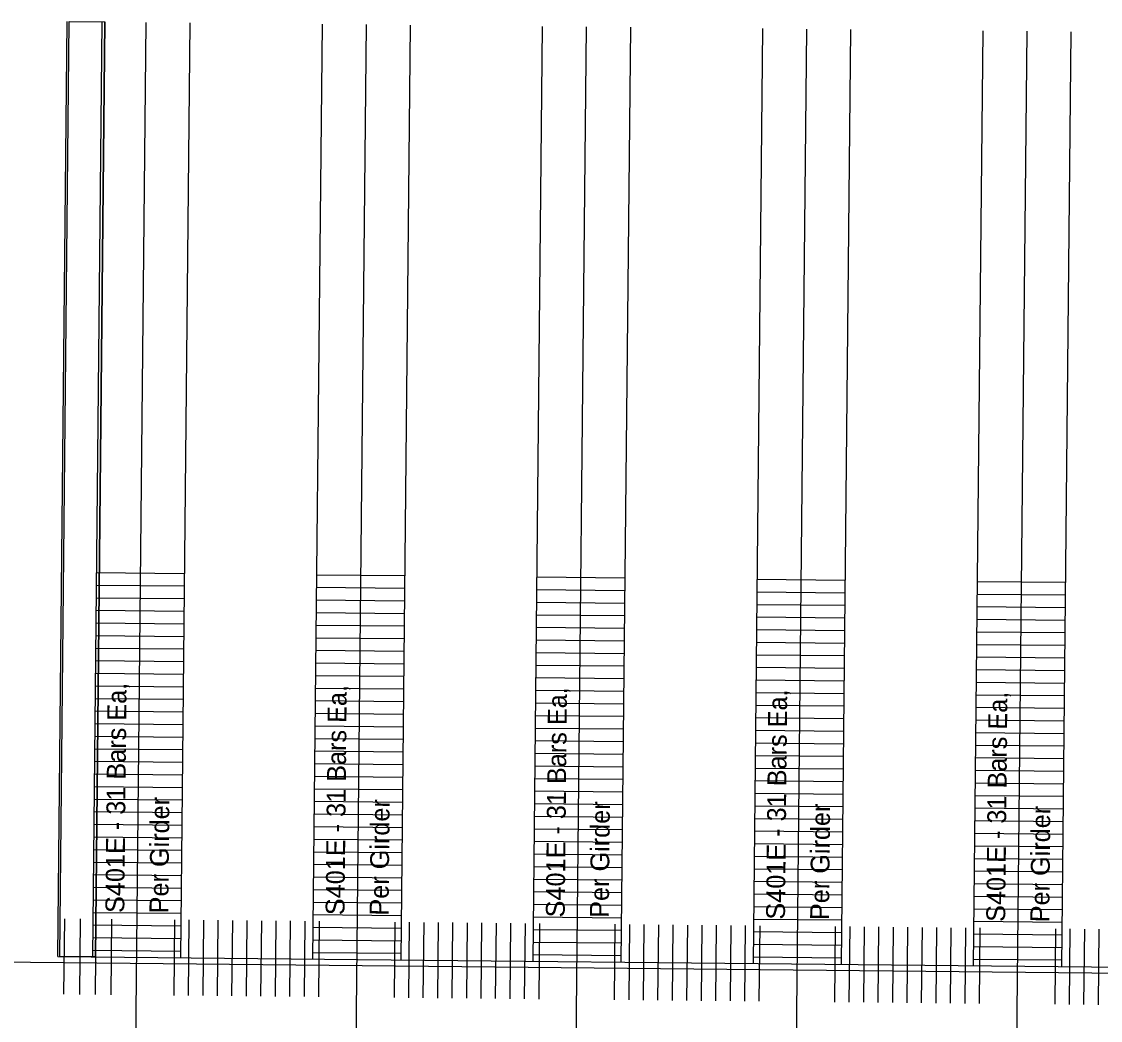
# Model space of a CAD drawing. Extents: x 632547 to 633311, y 380830 to 386139.
# Drawn here: x 633125.99 to 633168.86, y 380897.98 to 380937.66 of the extents above; entities that cross this region are included whole.
import ezdxf

# ---------------------------------------------------------------- set-up
doc = ezdxf.new("R2010")
doc.units = 0
for name, color, linetype in [('B_Border', 7, 'Continuous'), ('B_Boring Annot', 7, 'Continuous'), ('R_Border_Scale', 7, 'Continuous'), ('R_Wall', 7, 'Continuous')]:
    doc.layers.add(name, color=color, linetype=linetype)

msp = doc.modelspace()

# ---------------------------------------------------------------- linework, layer by layer
at = {"layer": 'B_Border'}
for p, q in [((633130.932, 380937.625), (633130.499, 380894.868)), ((633139.681, 380937.537), (633139.249, 380894.779)), ((633148.431, 380937.448), (633147.998, 380894.69)), ((633157.181, 380937.36), (633156.748, 380894.602)), ((633165.93, 380937.271), (633165.498, 380894.513)), ((633212.425, 380899.415), (633095.371, 380900.599))]:
    msp.add_line(p, q, dxfattribs=at)
at = {"layer": 'B_Boring Annot'}
for p, q in [((633127.431, 380900.525), (633127.807, 380937.657)), ((633127.515, 380900.524), (633127.89, 380937.656)), ((633129.182, 380937.643), (633128.806, 380900.511)), ((633128.931, 380900.51), (633129.307, 380937.642)), ((633132.682, 380937.607), (633132.306, 380900.476)), ((633137.932, 380937.554), (633137.556, 380900.423)), ((633141.431, 380937.519), (633141.056, 380900.387)), ((633146.681, 380937.466), (633146.305, 380900.334)), ((633150.181, 380937.43), (633149.805, 380900.299)), ((633155.431, 380937.377), (633155.055, 380900.246)), ((633158.93, 380937.342), (633158.555, 380900.21)), ((633164.18, 380937.289), (633163.805, 380900.157)), ((633167.68, 380937.253), (633167.304, 380900.122)), ((633127.431, 380900.525), (633212.427, 380899.665))]:
    msp.add_line(p, q, dxfattribs=at)
msp.add_lwpolyline([(633127.89, 380937.656), (633129.307, 380937.642), (633128.931, 380900.51), (633127.515, 380900.524)], close=True, dxfattribs=at)
at = {"layer": 'R_Border_Scale'}
for p, q in [((633132.46, 380915.725), (633128.961, 380915.76)), ((633141.21, 380915.636), (633137.71, 380915.672)), ((633149.96, 380915.548), (633146.46, 380915.583)), ((633132.455, 380915.225), (633128.956, 380915.26)), ((633141.205, 380915.136), (633137.705, 380915.172)), ((633158.709, 380915.459), (633155.209, 380915.495)), ((633167.459, 380915.371), (633163.959, 380915.406)), ((633132.45, 380914.725), (633128.951, 380914.76)), ((633149.955, 380915.048), (633146.455, 380915.083)), ((633158.704, 380914.959), (633155.204, 380914.995)), ((633167.454, 380914.871), (633163.954, 380914.906)), ((633141.2, 380914.636), (633137.7, 380914.672)), ((633149.949, 380914.548), (633146.45, 380914.583)), ((633158.699, 380914.459), (633155.199, 380914.495)), ((633167.449, 380914.371), (633163.949, 380914.406)), ((633132.445, 380914.225), (633128.945, 380914.26)), ((633141.195, 380914.136), (633137.695, 380914.172)), ((633149.944, 380914.048), (633146.445, 380914.083)), ((633158.694, 380913.959), (633155.194, 380913.995)), ((633167.443, 380913.871), (633163.944, 380913.906)), ((633132.44, 380913.725), (633128.94, 380913.76)), ((633141.19, 380913.637), (633137.69, 380913.672)), ((633149.939, 380913.548), (633146.44, 380913.583)), ((633158.689, 380913.459), (633155.189, 380913.495)), ((633132.435, 380913.225), (633128.935, 380913.26)), ((633141.185, 380913.137), (633137.685, 380913.172)), ((633149.934, 380913.048), (633146.434, 380913.083)), ((633158.684, 380912.96), (633155.184, 380912.995)), ((633167.438, 380913.371), (633163.939, 380913.406)), ((633132.43, 380912.725), (633128.93, 380912.76)), ((633141.18, 380912.637), (633137.68, 380912.672)), ((633149.929, 380912.548), (633146.429, 380912.583)), ((633167.433, 380912.871), (633163.934, 380912.906)), ((633132.425, 380912.225), (633128.925, 380912.261)), ((633141.175, 380912.137), (633137.675, 380912.172)), ((633158.679, 380912.46), (633155.179, 380912.495)), ((633167.428, 380912.371), (633163.928, 380912.406)), ((633132.42, 380911.725), (633128.92, 380911.761)), ((633149.924, 380912.048), (633146.424, 380912.083)), ((633158.674, 380911.96), (633155.174, 380911.995)), ((633167.423, 380911.871), (633163.923, 380911.906)), ((633141.17, 380911.637), (633137.67, 380911.672)), ((633149.919, 380911.548), (633146.419, 380911.584)), ((633158.669, 380911.46), (633155.169, 380911.495)), ((633167.418, 380911.371), (633163.918, 380911.406)), ((633132.415, 380911.225), (633128.915, 380911.261)), ((633141.164, 380911.137), (633137.665, 380911.172)), ((633149.914, 380911.048), (633146.414, 380911.084)), ((633158.664, 380910.96), (633155.164, 380910.995)), ((633167.413, 380910.871), (633163.913, 380910.906)), ((633132.41, 380910.725), (633128.91, 380910.761)), ((633141.159, 380910.637), (633137.66, 380910.672)), ((633149.909, 380910.548), (633146.409, 380910.584)), ((633158.659, 380910.46), (633155.159, 380910.495)), ((633132.405, 380910.225), (633128.905, 380910.261)), ((633141.154, 380910.137), (633137.655, 380910.172)), ((633149.904, 380910.048), (633146.404, 380910.084)), ((633158.653, 380909.96), (633155.154, 380909.995)), ((633167.408, 380910.371), (633163.908, 380910.407)), ((633132.4, 380909.725), (633128.9, 380909.761)), ((633141.149, 380909.637), (633137.649, 380909.672)), ((633149.899, 380909.548), (633146.399, 380909.584)), ((633167.403, 380909.871), (633163.903, 380909.907)), ((633132.395, 380909.225), (633128.895, 380909.261)), ((633141.144, 380909.137), (633137.644, 380909.172)), ((633158.648, 380909.46), (633155.149, 380909.495)), ((633167.398, 380909.371), (633163.898, 380909.407)), ((633132.39, 380908.725), (633128.89, 380908.761)), ((633149.894, 380909.048), (633146.394, 380909.084)), ((633158.643, 380908.96), (633155.144, 380908.995)), ((633167.393, 380908.871), (633163.893, 380908.907)), ((633141.139, 380908.637), (633137.639, 380908.672)), ((633149.889, 380908.548), (633146.389, 380908.584)), ((633158.638, 380908.46), (633155.138, 380908.495)), ((633167.388, 380908.371), (633163.888, 380908.407)), ((633132.385, 380908.225), (633128.885, 380908.261)), ((633141.134, 380908.137), (633137.634, 380908.172)), ((633149.884, 380908.048), (633146.384, 380908.084)), ((633158.633, 380907.96), (633155.133, 380907.995)), ((633167.383, 380907.871), (633163.883, 380907.907)), ((633132.38, 380907.725), (633128.88, 380907.761)), ((633141.129, 380907.637), (633137.629, 380907.672)), ((633149.879, 380907.548), (633146.379, 380907.584)), ((633158.628, 380907.46), (633155.128, 380907.495)), ((633132.374, 380907.225), (633128.875, 380907.261)), ((633141.124, 380907.137), (633137.624, 380907.172)), ((633149.874, 380907.048), (633146.374, 380907.084)), ((633158.623, 380906.96), (633155.123, 380906.995)), ((633167.378, 380907.371), (633163.878, 380907.407)), ((633132.369, 380906.725), (633128.87, 380906.761)), ((633141.119, 380906.637), (633137.619, 380906.672)), ((633149.869, 380906.548), (633146.369, 380906.584)), ((633167.373, 380906.871), (633163.873, 380906.907)), ((633132.364, 380906.225), (633128.865, 380906.261)), ((633141.114, 380906.137), (633137.614, 380906.172)), ((633158.618, 380906.46), (633155.118, 380906.495)), ((633167.368, 380906.371), (633163.868, 380906.407)), ((633132.359, 380905.725), (633128.859, 380905.761)), ((633149.863, 380906.048), (633146.364, 380906.084)), ((633158.613, 380905.96), (633155.113, 380905.995)), ((633167.363, 380905.871), (633163.863, 380905.907)), ((633141.109, 380905.637), (633137.609, 380905.672)), ((633149.858, 380905.548), (633146.359, 380905.584)), ((633158.608, 380905.46), (633155.108, 380905.495)), ((633167.357, 380905.371), (633163.858, 380905.407)), ((633132.354, 380905.225), (633128.854, 380905.261)), ((633141.104, 380905.137), (633137.604, 380905.172)), ((633149.853, 380905.048), (633146.354, 380905.084)), ((633158.603, 380904.96), (633155.103, 380904.995)), ((633167.352, 380904.871), (633163.853, 380904.907)), ((633132.349, 380904.726), (633128.849, 380904.761)), ((633141.099, 380904.637), (633137.599, 380904.672)), ((633149.848, 380904.548), (633146.348, 380904.584)), ((633158.598, 380904.46), (633155.098, 380904.495)), ((633132.344, 380904.226), (633128.844, 380904.261)), ((633141.094, 380904.137), (633137.594, 380904.172)), ((633149.843, 380904.048), (633146.343, 380904.084)), ((633158.593, 380903.96), (633155.093, 380903.995)), ((633167.347, 380904.371), (633163.848, 380904.407)), ((633132.339, 380903.726), (633128.839, 380903.761)), ((633141.089, 380903.637), (633137.589, 380903.672)), ((633149.838, 380903.549), (633146.338, 380903.584)), ((633167.342, 380903.871), (633163.843, 380903.907)), ((633132.334, 380903.226), (633128.834, 380903.261)), ((633141.084, 380903.137), (633137.584, 380903.172)), ((633158.588, 380903.46), (633155.088, 380903.495)), ((633167.337, 380903.371), (633163.837, 380903.407)), ((633132.329, 380902.726), (633128.829, 380902.761)), ((633149.833, 380903.049), (633146.333, 380903.084)), ((633158.583, 380902.96), (633155.083, 380902.995)), ((633167.332, 380902.871), (633163.832, 380902.907)), ((633141.078, 380902.637), (633137.579, 380902.672)), ((633149.828, 380902.549), (633146.328, 380902.584)), ((633158.578, 380902.46), (633155.078, 380902.495)), ((633167.327, 380902.372), (633163.827, 380902.407)), ((633127.697, 380902.022), (633127.666, 380899.023)), ((633128.322, 380902.016), (633128.291, 380899.016)), ((633132.324, 380902.226), (633128.824, 380902.261)), ((633128.947, 380902.01), (633128.916, 380899.01)), ((633129.571, 380902.003), (633129.541, 380899.004)), ((633132.071, 380901.978), (633132.041, 380898.978)), ((633132.646, 380901.972), (633132.616, 380898.973)), ((633133.221, 380901.967), (633133.191, 380898.967)), ((633133.796, 380901.961), (633133.766, 380898.961)), ((633134.371, 380901.955), (633134.341, 380898.955)), ((633134.946, 380901.949), (633134.916, 380898.949)), ((633135.521, 380901.943), (633135.491, 380898.943)), ((633136.096, 380901.937), (633136.066, 380898.938)), ((633136.671, 380901.932), (633136.641, 380898.932)), ((633137.246, 380901.926), (633137.216, 380898.926)), ((633141.073, 380902.137), (633137.574, 380902.173)), ((633137.821, 380901.92), (633137.791, 380898.92)), ((633140.821, 380901.89), (633140.791, 380898.89)), ((633141.396, 380901.884), (633141.366, 380898.884)), ((633141.971, 380901.878), (633141.941, 380898.878)), ((633142.546, 380901.872), (633142.515, 380898.872)), ((633143.121, 380901.866), (633143.09, 380898.867)), ((633143.696, 380901.861), (633143.665, 380898.861)), ((633144.271, 380901.855), (633144.24, 380898.855)), ((633144.846, 380901.849), (633144.815, 380898.849)), ((633149.823, 380902.049), (633146.323, 380902.084)), ((633158.573, 380901.96), (633155.073, 380901.995)), ((633167.322, 380901.872), (633163.822, 380901.907)), ((633132.319, 380901.726), (633128.819, 380901.761)), ((633141.068, 380901.637), (633137.569, 380901.673)), ((633145.421, 380901.843), (633145.39, 380898.843)), ((633145.996, 380901.837), (633145.965, 380898.837)), ((633149.818, 380901.549), (633146.318, 380901.584)), ((633146.571, 380901.831), (633146.54, 380898.832)), ((633149.57, 380901.801), (633149.54, 380898.801)), ((633150.145, 380901.795), (633150.115, 380898.795)), ((633150.72, 380901.789), (633150.69, 380898.79)), ((633151.295, 380901.784), (633151.265, 380898.784)), ((633151.87, 380901.778), (633151.84, 380898.778)), ((633152.445, 380901.772), (633152.415, 380898.772)), ((633153.02, 380901.766), (633152.99, 380898.766)), ((633153.595, 380901.76), (633153.565, 380898.761)), ((633154.17, 380901.755), (633154.14, 380898.755)), ((633154.745, 380901.749), (633154.715, 380898.749)), ((633158.567, 380901.46), (633155.068, 380901.496)), ((633155.32, 380901.743), (633155.29, 380898.743)), ((633158.32, 380901.713), (633158.29, 380898.713)), ((633158.895, 380901.707), (633158.865, 380898.707)), ((633159.47, 380901.701), (633159.44, 380898.701)), ((633160.045, 380901.695), (633160.015, 380898.695)), ((633160.62, 380901.689), (633160.59, 380898.689)), ((633161.195, 380901.684), (633161.165, 380898.684)), ((633161.77, 380901.678), (633161.739, 380898.678)), ((633162.345, 380901.672), (633162.314, 380898.672)), ((633162.92, 380901.666), (633162.889, 380898.666)), ((633163.495, 380901.66), (633163.464, 380898.66)), ((633164.07, 380901.654), (633164.039, 380898.655)), ((633167.07, 380901.624), (633167.039, 380898.624)), ((633167.645, 380901.618), (633167.614, 380898.618)), ((633168.22, 380901.612), (633168.189, 380898.613)), ((633168.794, 380901.607), (633168.764, 380898.607)), ((633132.314, 380901.226), (633128.814, 380901.261)), ((633141.063, 380901.137), (633137.563, 380901.173)), ((633149.813, 380901.049), (633146.313, 380901.084)), ((633158.562, 380900.96), (633155.063, 380900.996)), ((633167.317, 380901.372), (633163.817, 380901.407)), ((633132.309, 380900.726), (633128.809, 380900.761)), ((633141.058, 380900.637), (633137.558, 380900.673)), ((633149.808, 380900.549), (633146.308, 380900.584)), ((633167.312, 380900.872), (633163.812, 380900.907)), ((633158.557, 380900.46), (633155.058, 380900.496)), ((633167.307, 380900.372), (633163.807, 380900.407))]:
    msp.add_line(p, q, dxfattribs=at)

# ---------------------------------------------------------------- texts
at = {"layer": 'R_Wall'}
for s, p in [('S401E - 31 Bars Ea,', (633130.074, 380902.248)), ('S401E - 31 Bars Ea,', (633138.824, 380902.16)), ('S401E - 31 Bars Ea,', (633147.573, 380902.071)), ('S401E - 31 Bars Ea,', (633156.323, 380901.983)), ('S401E - 31 Bars Ea,', (633165.072, 380901.894)), ('Per Girder', (633131.824, 380902.231)), ('Per Girder', (633140.573, 380902.142)), ('Per Girder', (633149.323, 380902.054)), ('Per Girder', (633158.073, 380901.965)), ('Per Girder', (633166.822, 380901.877))]:
    msp.add_text(s, height=0.75, rotation=89.4304, dxfattribs=at).set_placement(p)

doc.saveas('drawing.dxf')
